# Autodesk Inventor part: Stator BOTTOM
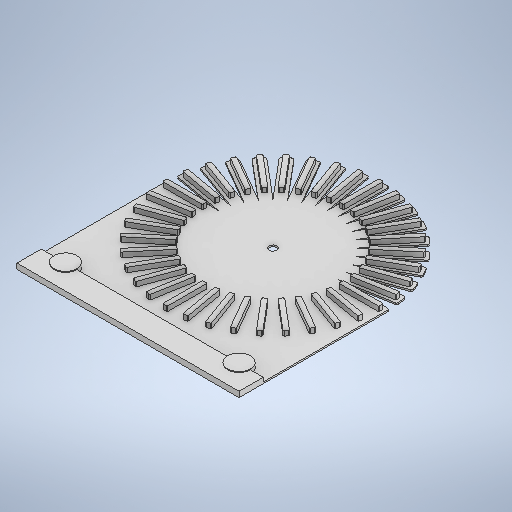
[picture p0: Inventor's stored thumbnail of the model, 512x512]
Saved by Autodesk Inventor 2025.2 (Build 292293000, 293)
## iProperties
Created: 2025-04
Part Number: Stator BOTTOM
Material: Generic
Document SubType Name: Modeling
Designer: bensa
Density: 1 g/cm^3
Appearance: Default
Author: bensa
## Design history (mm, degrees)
sketch "Sketch1"
  geometry: L1 (-143.5, 6.85)-(143.5, 6.85); L2 (145.5, 4.85)-(145.5, -4.85); L3 (143.5, -6.85)-(-143.5, -6.85); L4 (-145.5, -4.85)-(-145.5, 4.85); L5 (-143.406, 6.751)-(145.5, -6.85); L6 (145.5, 6.85)-(-145.5, -6.85); L7 (-6.85, 143.5)-(-6.85, -143.5); L8 (-4.85, -145.5)-(4.85, -145.5); L9 (6.85, -143.5)-(6.85, 143.5); L10 (4.85, 145.5)-(-4.85, 145.5); L11 (-6.85, 145.5)-(6.85, -145.5); L12 (-6.85, -145.5)-(6.85, 145.5); L13 (-140.13, 31.664)-(142.509, -18.173); L14 (144.132, -20.489)-(142.447, -30.042); L15 (140.13, -31.664)-(-142.509, 18.173); L16 (-144.132, 20.489)-(-142.447, 30.042); L17 (-142.1, 32.012)-(142.1, -32.012); L18 (144.479, -18.52)-(-144.479, 18.52); L19 (-142.1, 32.012)-(144.9, 32.012); L20 (-137.189, 42.643)-(132.503, -55.517); L21 (135.066, -54.321)-(138.384, -45.206); L22 (137.189, -42.643)-(-132.503, 55.517); L23 (-135.066, 54.321)-(-138.384, 45.206); L24 (-139.068, 43.327)-(139.068, -43.327); L25 (134.382, -56.201)-(-134.382, 56.201); L26 (-139.068, 43.327)-(147.932, 43.327); L27 (-127.7, 65.818)-(120.85, -77.682); L28 (123.582, -76.95)-(128.432, -68.55); L29 (127.7, -65.818)-(-120.85, 77.682); L30 (-123.582, 76.95)-(-128.432, 68.55); L31 (-129.432, 66.818)-(129.432, -66.818); L32 (122.582, -78.682)-(-120.817, 77.55); L33 (-114.33, 86.993)-(105.524, -97.487); L34 (108.342, -97.241)-(114.577, -89.81); L35 (114.33, -86.993)-(-105.524, 97.487); L36 (-108.342, 97.241)-(-114.577, 89.81); L37 (-115.863, 88.278)-(115.863, -88.278); L38 (107.056, -98.773)-(-105.516, 97.351); L39 (-97.487, 105.524)-(86.993, -114.33); L40 (89.81, -114.577)-(97.241, -108.342); L41 (97.487, -105.524)-(-86.993, 114.33); L42 (-89.81, 114.577)-(-97.241, 108.342); L43 (-98.773, 107.056)-(98.773, -107.056); L44 (87.008, -114.195)-(-88.278, 115.863); L45 (-77.682, 120.85)-(65.818, -127.7); L46 (68.55, -128.432)-(76.95, -123.582); L47 (77.682, -120.85)-(-65.818, 127.7); L48 (-68.55, 128.432)-(-76.95, 123.582); L49 (-78.682, 122.582)-(78.682, -122.582); L50 (66.818, -129.432)-(-66.818, 129.432); L51 (-55.517, 132.503)-(42.643, -137.189); L52 (45.206, -138.384)-(54.321, -135.066); L53 (55.517, -132.503)-(-42.643, 137.189); L54 (-45.206, 138.384)-(-54.321, 135.066); L55 (-56.201, 134.382)-(56.201, -134.382); L56 (43.327, -139.068)-(-43.327, 139.068); L57 (-31.664, 140.13)-(18.173, -142.509); L58 (20.489, -144.132)-(30.042, -142.447); L59 (31.664, -140.13)-(-18.173, 142.509); L60 (-20.489, 144.132)-(-30.042, 142.447); L61 (-32.012, 142.1)-(32.012, -142.1); L62 (18.52, -144.479)-(-18.52, 144.479); L63 (18.173, 142.509)-(-31.664, -140.13); L64 (-30.042, -142.447)-(-20.489, -144.132)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; A1 r 2 centre (113.045, 88.525) between (114.33, 86.993) and (114.577, 89.81); A2 r 2 centre (121.85, 75.95) between (123.582, 76.95) and (120.85, 77.682); A3 r 2 centre (126.7, 67.55) between (127.7, 65.818) and (128.432, 68.55); A4 r 2 centre (133.187, 53.637) between (135.066, 54.321) and (132.503, 55.517); A5 r 2 centre (136.505, 44.522) between (137.189, 42.643) and (138.384, 45.206); A6 r 2 centre (140.478, 29.695) between (142.447, 30.042) and (140.13, 31.664); A7 r 2 centre (142.162, 20.142) between (142.509, 18.173) and (144.132, 20.489); A8 r 2 centre (143.5, 4.85) between (145.5, 4.85) and (143.5, 6.85); A9 r 2 centre (143.5, -4.85) between (143.5, -6.85) and (145.5, -4.85); A10 r 2 centre (142.162, -20.142) between (144.132, -20.489) and (142.509, -18.173); A11 r 2 centre (140.478, -29.695) between (140.13, -31.664) and (142.447, -30.042); A12 r 2 centre (136.505, -44.522) between (138.384, -45.206) and (137.189, -42.643); A13 r 2 centre (133.187, -53.637) between (132.503, -55.517) and (135.066, -54.321); A14 r 2 centre (126.7, -67.55) between (128.432, -68.55) and (127.7, -65.818); A15 r 2 centre (121.85, -75.95) between (120.85, -77.682) and (123.582, -76.95); A16 r 2 centre (113.045, -88.525) between (114.577, -89.81) and (114.33, -86.993); A17 r 2 centre (106.81, -95.955) between (105.524, -97.487) and (108.342, -97.241); A18 r 2 centre (95.955, -106.81) between (97.241, -108.342) and (97.487, -105.524); A19 r 2 centre (75.95, -121.85) between (76.95, -123.582) and (77.682, -120.85); A20 r 2 centre (67.55, -126.7) between (65.818, -127.7) and (68.55, -128.432); A21 r 2 centre (53.637, -133.187) between (54.321, -135.066) and (55.517, -132.503); A22 r 2 centre (44.522, -136.505) between (42.643, -137.189) and (45.206, -138.384); A23 r 2 centre (29.695, -140.478) between (30.042, -142.447) and (31.664, -140.13); A24 r 2 centre (20.142, -142.162) between (18.173, -142.509) and (20.489, -144.132); A25 r 2 centre (4.85, -143.5) between (4.85, -145.5) and (6.85, -143.5); A26 r 2 centre (-4.85, -143.5) between (-6.85, -143.5) and (-4.85, -145.5); A27 r 2 centre (-20.142, -142.162) between (-20.489, -144.132) and (-18.173, -142.509); A28 r 2 centre (-29.695, -140.478) between (-31.664, -140.13) and (-30.042, -142.447); A29 r 2 centre (-44.522, -136.505) between (-45.206, -138.384) and (-42.643, -137.189); A30 r 2 centre (-53.637, -133.187) between (-55.517, -132.503) and (-54.321, -135.066); A31 r 2 centre (-67.55, -126.7) between (-68.55, -128.432) and (-65.818, -127.7); A32 r 2 centre (-75.95, -121.85) between (-77.682, -120.85) and (-76.95, -123.582); A33 r 2 centre (-88.525, -113.045) between (-89.81, -114.577) and (-86.993, -114.33); A34 r 2 centre (-95.955, -106.81) between (-97.487, -105.524) and (-97.241, -108.342); A35 r 2 centre (-106.81, -95.955) between (-108.342, -97.241) and (-105.524, -97.487); A36 r 2 centre (-113.045, -88.525) between (-114.33, -86.993) and (-114.577, -89.81); A37 r 2 centre (-121.85, -75.95) between (-123.582, -76.95) and (-120.85, -77.682); A38 r 2 centre (-126.7, -67.55) between (-127.7, -65.818) and (-128.432, -68.55); A39 r 2 centre (-136.505, -44.522) between (-137.189, -42.643) and (-138.384, -45.206); A40 r 2 centre (-140.478, -29.695) between (-142.447, -30.042) and (-140.13, -31.664); A41 r 2 centre (-142.162, -20.142) between (-142.509, -18.173) and (-144.132, -20.489); A42 r 2 centre (-143.5, -4.85) between (-145.5, -4.85) and (-143.5, -6.85); A43 r 2 centre (-142.162, 20.142) between (-144.132, 20.489) and (-142.509, 18.173); A44 r 2 centre (-140.478, 29.695) between (-140.13, 31.664) and (-142.447, 30.042); A45 r 2 centre (-136.505, 44.522) between (-138.384, 45.206) and (-137.189, 42.643); A46 r 2 centre (-133.187, 53.637) between (-132.503, 55.517) and (-135.066, 54.321); A47 r 2 centre (-126.7, 67.55) between (-128.432, 68.55) and (-127.7, 65.818); A48 r 2 centre (-113.045, 88.525) between (-114.577, 89.81) and (-114.33, 86.993); A49 r 2 centre (-95.955, 106.81) between (-97.241, 108.342) and (-97.487, 105.524); A50 r 2 centre (-88.525, 113.045) between (-86.993, 114.33) and (-89.81, 114.577); A51 r 2 centre (-75.95, 121.85) between (-76.95, 123.582) and (-77.682, 120.85); A52 r 2 centre (-67.55, 126.7) between (-65.818, 127.7) and (-68.55, 128.432); A53 r 2 centre (-53.637, 133.187) between (-54.321, 135.066) and (-55.517, 132.503); A54 r 2 centre (-44.522, 136.505) between (-42.643, 137.189) and (-45.206, 138.384); A55 r 2 centre (-29.695, 140.478) between (-30.042, 142.447) and (-31.664, 140.13); A56 r 2 centre (-20.142, 142.162) between (-18.173, 142.509) and (-20.489, 144.132); A57 r 2 centre (-4.85, 143.5) between (-4.85, 145.5) and (-6.85, 143.5); A58 r 2 centre (4.85, 143.5) between (6.85, 143.5) and (4.85, 145.5); A59 r 2 centre (20.142, 142.162) between (20.489, 144.132) and (18.173, 142.509); A60 r 2 centre (29.695, 140.478) between (31.664, 140.13) and (30.042, 142.447); A61 r 2 centre (44.522, 136.505) between (45.206, 138.384) and (42.643, 137.189); A62 r 2 centre (53.637, 133.187) between (55.517, 132.503) and (54.321, 135.066); A63 r 2 centre (67.55, 126.7) between (68.55, 128.432) and (65.818, 127.7); A64 r 2 centre (75.95, 121.85) between (77.682, 120.85) and (76.95, 123.582)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; 45 further points
  constraints: 220 end point, 158 point on line, 144 point on circle, 144 tangent, 72 centre point, 36 equal radius, 36 parallel, 31 midpoint, 19 perpendicular, 3 horizontal, 2 equal length, 1 vertical
  dimensions: "d1" = 13.7 distance of L6.start L5.end; "d52" = 2 radius of A9 (derived); "d53" = 2 radius of A23 (derived); "d54" = 2 radius of A60 (derived); "d58" = 2 radius of A66 (derived); "d59" = 2 radius of A67 (derived); "d60" = 2 radius of A68 (derived); "d61" = 2 radius of A69 (derived); "d62" = 2 radius of A70 (derived); "d63" = 2 radius of A71 (derived); "d64" = 2 radius of A72 (derived)
sketch "Sketch2"
  geometry: L1 (-145.5, 190)-(-145.5, 0); L2 (-145.5, 0)-(145.5, 0); L3 (145.5, 0)-(145.5, 190); L4 (145.5, 190)-(-145.5, 190); L5 (-145.5, 190)-(145.5, 0); L6 (-145.5, 0)-(145.5, 190); 2 further points
  constraints: 12 end point, 2 midpoint, 2 parallel, 1 perpendicular
extrude "Extrusion1" new body sketch "Sketch1" distance "d65" = 2; taper "d66" = 0 deg
sketch "Sketch4"
  geometry: L1 (142.509, -18.173)-(78.296, -6.85) reference; L2 (64.381, -45.08)-(114.33, -86.993) reference; L3 (42.643, -137.189)-(20.342, -75.917) reference; L4 (18.173, 142.509)-(6.85, 78.296) reference; L5 (2, 141.65)-(-2, 141.65); L6 (31.664, 140.13)-(20.342, 75.917) reference; L7 (45.628, 134.134)-(50.327, 132.423); L8 (20.342, 75.917)-(42.643, 137.189) reference; L9 (68.857, 123.808)-(73.188, 121.308); L10 (-72.557, 121.672)-(-69.093, 123.672); L11 (-65.818, 127.7)-(-33.216, 71.231) reference; L12 (-50.327, 132.423)-(-46.568, 133.792); L13 (-42.643, 137.189)-(-20.342, 75.917) reference; L14 (-26.567, 139.151)-(-22.628, 139.845); L15 (-18.173, 142.509)-(-6.85, 78.296) reference; L16 (89.519, 109.796)-(93.349, 106.582); L17 (45.08, 64.381)-(86.993, 114.33) reference; L18 (106.582, 93.349)-(109.796, 89.519); L19 (121.672, 72.557)-(123.672, 69.093); L20 (71.231, 33.216)-(127.7, 65.818) reference; L21 (132.423, 50.327)-(133.792, 46.568); L22 (139.151, 26.567)-(139.845, 22.628); L23 (75.917, 20.342)-(140.13, 31.664) reference; L24 (141.65, 2)-(141.65, -2); L25 (143.5, -6.85)-(78.296, -6.85) reference; L26 (132.081, -51.266)-(134.134, -45.628); L27 (107.225, -92.583)-(109.796, -89.519); L28 (121.672, -72.557)-(124.172, -68.227); L29 (89.519, -109.796)-(92.583, -107.225); L30 (69.093, -123.672)-(72.557, -121.672); L31 (46.568, -133.792)-(50.327, -132.423); L32 (22.628, -139.845)-(26.567, -139.151); L33 (-2, -141.65)-(2, -141.65); L34 (-26.567, -139.151)-(-22.628, -139.845); L35 (-73.188, -121.308)-(-68.857, -123.808); L36 (-50.327, -132.423)-(-46.568, -133.792); L37 (-92.583, -107.225)-(-89.519, -109.796); L38 (-109.796, -89.519)-(-107.225, -92.583); L39 (-123.672, -69.093)-(-121.672, -72.557); L40 (-133.792, -46.568)-(-132.423, -50.327); L41 (-141.65, -2)-(-141.65, 2); L42 (-139.845, 22.628)-(-139.151, 26.567); L43 (-133.792, 46.568)-(-132.423, 50.327); L44 (-124.172, 68.227)-(-121.172, 73.423); L45 (-109.796, 89.519)-(-107.225, 92.583); L46 (-89.519, 109.796)-(-92.583, 107.225); L47 (-27.552, 138.977)-(-21.643, 140.019); L48 (-21.469, 139.034)-(-12.735, 89.498); L49 (-13.546, 88.34)-(-17.485, 87.645); L50 (-18.644, 88.456)-(-27.378, 137.992); L51 (-3, 141.65)-(3, 141.65); L52 (3, 140.65)-(3, 90.35); L53 (2, 89.35)-(-2, 89.35); L54 (-3, 90.35)-(-3, 140.65); L55 (22.628, 139.845)-(27.552, 138.977); L56 (21.643, 140.019)-(26.567, 139.151); L57 (27.378, 137.992)-(18.644, 88.456); L58 (17.485, 87.645)-(13.546, 88.34); L59 (12.735, 89.498)-(21.469, 139.034); L60 (46.568, 133.792)-(51.266, 132.081); L61 (50.924, 131.142)-(33.721, 83.875); L62 (32.439, 83.277)-(28.68, 84.646); L63 (28.082, 85.927)-(45.286, 133.194); L64 (67.991, 124.308)-(72.321, 121.808)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; A1 r 1 centre (-138.166, 26.393) between (-137.992, 27.378) and (-139.151, 26.567); A2 r 1 centre (-88.63, 17.659) between (-87.645, 17.485) and (-88.456, 18.644); A3 r 1 centre (-89.325, 13.719) between (-89.498, 12.735) and (-88.34, 13.546); A4 r 1 centre (-138.861, 22.454) between (-139.845, 22.628) and (-139.034, 21.469); A5 r 1 centre (-132.852, 46.226) between (-133.792, 46.568) and (-133.194, 45.286); A6 r 1 centre (-131.484, 49.985) between (-131.142, 50.924) and (-132.423, 50.327); A7 r 1 centre (-84.217, 32.781) between (-83.277, 32.439) and (-83.875, 33.721); A8 r 1 centre (-85.585, 29.022) between (-85.927, 28.082) and (-84.646, 28.68); A9 r 1 centre (-79.245, 43.443) between (-79.745, 42.577) and (-78.379, 42.943); A10 r 1 centre (-122.806, 68.593) between (-123.672, 69.093) and (-123.306, 67.727); A11 r 1 centre (-120.806, 72.057) between (-120.306, 72.923) and (-121.672, 72.557); A12 r 1 centre (-77.245, 46.907) between (-76.379, 46.407) and (-76.745, 47.773); A13 r 1 centre (-109.03, 88.876) between (-109.796, 89.519) and (-109.673, 88.11); A14 r 1 centre (-106.459, 91.94) between (-105.816, 92.706) and (-107.225, 92.583); A15 r 1 centre (-67.927, 59.608) between (-67.16, 58.965) and (-67.284, 60.374); A16 r 1 centre (-70.498, 56.544) between (-71.14, 55.778) and (-69.732, 55.901); A17 r 1 centre (-91.94, 106.459) between (-92.583, 107.225) and (-92.706, 105.816); A18 r 1 centre (-56.544, 70.498) between (-55.901, 69.732) and (-55.778, 71.14); A19 r 1 centre (-56.544, 70.498) between (-55.901, 69.732) and (-55.778, 71.14); A20 r 1 centre (-59.608, 67.927) between (-60.374, 67.284) and (-58.965, 67.16); A21 r 1 centre (-88.876, 109.03) between (-88.11, 109.673) and (-89.519, 109.796); A22 r 1 centre (-72.057, 120.806) between (-72.557, 121.672) and (-72.923, 120.306); A23 r 1 centre (-68.593, 122.806) between (-67.727, 123.306) and (-69.093, 123.672); A24 r 1 centre (-43.443, 79.245) between (-42.943, 78.379) and (-42.577, 79.745); A25 r 1 centre (-46.907, 77.245) between (-47.773, 76.745) and (-46.407, 76.379); A26 r 1 centre (-49.985, 131.484) between (-50.327, 132.423) and (-50.924, 131.142); A27 r 1 centre (-46.226, 132.852) between (-45.286, 133.194) and (-46.568, 133.792); A28 r 1 centre (-29.022, 85.585) between (-28.68, 84.646) and (-28.082, 85.927); A29 r 1 centre (-32.781, 84.217) between (-33.721, 83.875) and (-32.439, 83.277); A30 r 1 centre (-17.659, 88.63) between (-18.644, 88.456) and (-17.485, 87.645); A31 r 1 centre (-26.393, 138.166) between (-26.567, 139.151) and (-27.378, 137.992); A32 r 1 centre (-22.454, 138.861) between (-21.469, 139.034) and (-22.628, 139.845); A33 r 1 centre (-13.719, 89.325) between (-13.546, 88.34) and (-12.735, 89.498); A34 r 1 centre (-2, 140.65) between (-2, 141.65) and (-3, 140.65); A35 r 1 centre (2, 140.65) between (3, 140.65) and (2, 141.65); A36 r 1 centre (2, 90.35) between (2, 89.35) and (3, 90.35); A37 r 1 centre (-2, 90.35) between (-3, 90.35) and (-2, 89.35); A38 r 1 centre (22.454, 138.861) between (22.628, 139.845) and (21.469, 139.034); A39 r 1 centre (26.393, 138.166) between (27.378, 137.992) and (26.567, 139.151); A40 r 1 centre (13.719, 89.325) between (12.735, 89.498) and (13.546, 88.34); A41 r 1 centre (17.659, 88.63) between (17.485, 87.645) and (18.644, 88.456); A42 r 1 centre (29.022, 85.585) between (28.082, 85.927) and (28.68, 84.646); A43 r 1 centre (46.226, 132.852) between (46.568, 133.792) and (45.286, 133.194); A44 r 1 centre (49.985, 131.484) between (50.924, 131.142) and (50.327, 132.423); A45 r 1 centre (32.781, 84.217) between (32.439, 83.277) and (33.721, 83.875); A46 r 1 centre (43.207, 79.381) between (42.341, 79.881) and (42.707, 78.515); A47 r 1 centre (68.357, 122.942) between (68.857, 123.808) and (67.491, 123.442); A48 r 1 centre (71.821, 120.942) between (72.688, 120.442) and (72.321, 121.808); A49 r 1 centre (46.671, 77.381) between (46.171, 76.515) and (47.538, 76.881); A50 r 1 centre (56.544, 70.498) between (55.778, 71.14) and (55.901, 69.732); A51 r 1 centre (88.876, 109.03) between (89.519, 109.796) and (88.11, 109.673); A52 r 1 centre (91.94, 106.459) between (92.706, 105.816) and (92.583, 107.225); A53 r 1 centre (59.608, 67.927) between (58.965, 67.16) and (60.374, 67.284); A54 r 1 centre (67.927, 59.608) between (67.284, 60.374) and (67.16, 58.965); A55 r 1 centre (106.459, 91.94) between (107.225, 92.583) and (105.816, 92.706); A56 r 1 centre (109.03, 88.876) between (109.673, 88.11) and (109.796, 89.519); A57 r 1 centre (70.498, 56.544) between (69.732, 55.901) and (71.14, 55.778); A58 r 1 centre (77.245, 46.907) between (76.745, 47.773) and (76.379, 46.407); A59 r 1 centre (120.806, 72.057) between (121.672, 72.557) and (120.306, 72.923); A60 r 1 centre (122.806, 68.593) between (123.306, 67.727) and (123.672, 69.093); A61 r 1 centre (79.245, 43.443) between (78.379, 42.943) and (79.745, 42.577); A62 r 1 centre (84.217, 32.781) between (83.875, 33.721) and (83.277, 32.439); A63 r 1 centre (131.484, 49.985) between (132.423, 50.327) and (131.142, 50.924); A64 r 1 centre (132.852, 46.226) between (133.194, 45.286) and (133.792, 46.568)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; 15 further points
  constraints: 360 end point, 290 point on circle, 290 tangent, 146 point on line, 145 centre point, 141 equal radius, 73 parallel, 45 perpendicular, 31 collinear, 2 horizontal, 1 vertical
extrude "Extrusion2" join sketch "Sketch2" distance "d268" = 2; taper "d269" = 0 deg
sketch "Sketch5"
  geometry: L1 (145.5, -190)-(-145.5, -190) reference; L2 (-145.5, -190)-(-113.68, -158.18); L3 (-145.5, -190)-(-100.5, -190); L4 (145.5, -190)-(113.68, -158.18); L5 (145.5, -190)-(190.5, -190); L6 (-145.5, -190)-(-145.5, 4.85) reference; L7 (145.5, 0)-(145.5, -190); L8 (145.5, -190)-(-145.5, -190); L9 (-145.5, -190)-(-145.5, 0); C1 r 15 at (-113.68, -158.18); C2 r 15 at (113.68, -158.18); A1 r 145.5 centre (0, 0) between (-145.5, 0) and (145.5, 0); 1 further point
  constraints: 14 end point, 3 centre point, 3 coincident, 2 equal length, 2 horizontal, 2 point on circle, 1 parallel, 1 point on line
  dimensions: "d270" = 45 distance of L1.end L2.end; "d271" = 45 deg angle of L3 L2; "d272" = 45 distance of L1.start L4.end; "d273" = 135 deg angle of L5 L4; "d274" = 30 diameter of C1; "d275" = 30 diameter of C2
extrude "Extrusion3" join sketch "Sketch5" distance "d276" = 6.25; taper "d277" = 0 deg
sketch "Sketch6"
  geometry: L1 (-145.5, 4.85)-(-145.5, -190) reference; L2 (-145.5, 0)-(-145.5, -190); L3 (-145.5, -190)-(145.5, -190); L4 (145.5, -190)-(145.5, 0); L5 (-145.5, -158.18)-(145.5, -158.18); L6 (145.5, -158.18)-(145.5, -190); L7 (145.5, -190)-(-145.5, -190); L8 (-145.5, -190)-(-145.5, -158.18); C1 r 15 at (-113.68, -158.18) reference; A1 r 145.5 centre (0, 0) between (-145.5, 0) and (145.5, 0); 4 further points
  constraints: 14 end point, 3 parallel, 3 perpendicular, 3 point on line, 2 point on circle, 1 centre point, 1 coincident, 1 collinear
extrude "Extrusion4" join sketch "Sketch6" distance "d281" = 5.25; taper "d282" = 0 deg
extrude "Extrusion5" join sketch "Sketch4" distance "d283" = 6.25; taper "d284" = 0 deg
sketch "Sketch7"
  geometry: C1 r 5 at (0, 0); 1 further point
  constraints: 1 centre point, 1 coincident
  dimensions: "d285" = 10 diameter of C1
extrude "Extrusion6" cut sketch "Sketch7" distance "d286" = 6.25; taper "d287" = 0 deg
body "Solid1"
